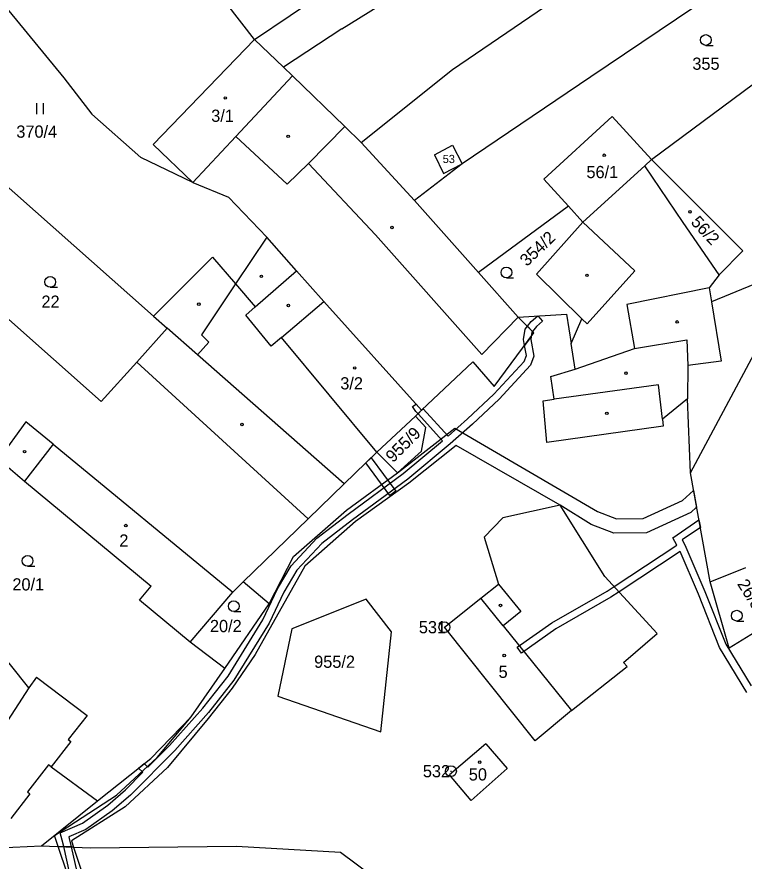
# Model space of a CAD drawing. Extents: x -749173 to -746119, y -1132678 to -1130338.
# Drawn here: x -747928.4 to -747827.1, y -1130958.5 to -1130840.9 of the extents above; entities that cross this region are included whole.
import ezdxf

# ---------------------------------------------------------------- set-up
doc = ezdxf.new("R2010")
doc.units = 0
for name, color, linetype in [('Vrstva 1', 7, 'Continuous'), ('Vrstva 17', 7, 'Continuous'), ('Vrstva 18', 7, 'Continuous'), ('Vrstva 19', 7, 'Continuous'), ('Vrstva 24', 7, 'Continuous'), ('Vrstva 25', 7, 'Continuous'), ('Vrstva 3', 7, 'Continuous'), ('Vrstva 30', 7, 'Continuous'), ('Vrstva 37', 7, 'Continuous'), ('Vrstva 4', 7, 'Continuous'), ('Vrstva 6', 7, 'Continuous'), ('Vrstva 62', 7, 'Continuous')]:
    doc.layers.add(name, color=color, linetype=linetype)

msp = doc.modelspace()

# ---------------------------------------------------------------- linework, layer by layer
at = {"layer": 'Vrstva 1'}
for p, q in [((-747831.83, -1130919.6), (-747826.88, -1130917.6)), ((-747829.18, -1130928.84), (-747831.83, -1130919.6)), ((-747822.73, -1130924.82), (-747829.18, -1130928.84))]:
    msp.add_line(p, q, dxfattribs=at)
for points in [[(-747867.74, -1130848.23), (-747820.55, -1130816.09)], [(-747812.81, -1130825.22), (-747848.46, -1130849.27)], [(-747937.23, -1130830.7), (-747921.89, -1130849.4)], [(-747840.03, -1130860.79), (-747804.38, -1130834.32)], [(-747895.31, -1130844.05), (-747899.19, -1130839.1)], [(-747895.31, -1130844.05), (-747909.44, -1130858.68)], [(-747891.29, -1130847.94), (-747895.31, -1130844.05)], [(-747890.05, -1130849.13), (-747891.29, -1130847.94)], [(-747880.46, -1130858.39), (-747867.74, -1130848.23)], [(-747921.89, -1130849.4), (-747917.99, -1130854.46)], [(-747890.05, -1130849.13), (-747882.73, -1130856.2)], [(-747848.46, -1130849.27), (-747866.39, -1130861.37)], [(-747917.99, -1130854.46), (-747911.17, -1130860.49)], [(-747845.48, -1130854.8), (-747855.03, -1130863.49)], [(-747845.48, -1130854.8), (-747840.03, -1130860.79)], [(-747880.46, -1130858.39), (-747882.73, -1130856.2)], [(-747909.44, -1130858.68), (-747903.93, -1130864)], [(-747880.46, -1130858.39), (-747873.03, -1130866.5)], [(-747870.26, -1130860.14), (-747867.74, -1130858.78)], [(-747867.74, -1130858.78), (-747866.39, -1130861.37)], [(-747870.26, -1130860.14), (-747868.98, -1130862.72)], [(-747903.93, -1130864), (-747911.17, -1130860.49)], [(-747840.03, -1130860.79), (-747840.96, -1130861.66)], [(-747840.03, -1130860.79), (-747827.3, -1130873.5)], [(-747866.39, -1130861.37), (-747873.03, -1130866.5)], [(-747868.98, -1130862.72), (-747866.39, -1130861.37)], [(-747835.61, -1130869.57), (-747840.96, -1130861.66)], [(-747931.2, -1130863.28), (-747912.7, -1130879.65)], [(-747851.6, -1130867.26), (-747855.03, -1130863.49)], [(-747903.93, -1130864), (-747898.96, -1130866.03)], [(-747893.59, -1130871.58), (-747898.96, -1130866.03)], [(-747864.12, -1130876.49), (-747873.03, -1130866.5)], [(-747851.6, -1130867.26), (-747864.12, -1130876.49)], [(-747849.58, -1130869.48), (-747851.6, -1130867.26)], [(-747849.58, -1130869.48), (-747856.02, -1130876.74)], [(-747830.59, -1130876.82), (-747835.61, -1130869.57)], [(-747893.59, -1130871.58), (-747897.97, -1130878.1)], [(-747889.47, -1130876.3), (-747893.59, -1130871.58)], [(-747827.3, -1130873.5), (-747830.59, -1130876.82)], [(-747909.4, -1130882.58), (-747901.18, -1130874.36)], [(-747901.18, -1130874.36), (-747897.97, -1130878.1)], [(-747889.47, -1130876.3), (-747885.64, -1130880.57)], [(-747858.58, -1130882.72), (-747864.12, -1130876.49)], [(-747916.7, -1130894.49), (-747936.25, -1130877.17)], [(-747856.02, -1130876.74), (-747849.73, -1130882.95)], [(-747830.59, -1130876.82), (-747832, -1130878.65)], [(-747832, -1130878.65), (-747831.64, -1130880.59)], [(-747825.65, -1130878.15), (-747831.64, -1130880.59)], [(-747912.7, -1130879.65), (-747909.4, -1130882.58)], [(-747885.64, -1130880.57), (-747872.04, -1130895.7)], [(-747831.64, -1130880.59), (-747830.29, -1130888.84)], [(-747858.58, -1130882.72), (-747851.86, -1130882.31)], [(-747851.86, -1130882.31), (-747851.22, -1130886.4)], [(-747909.4, -1130882.58), (-747907.48, -1130884.27)], [(-747856.4, -1130884.91), (-747858.58, -1130882.72)], [(-747851.22, -1130886.4), (-747849.73, -1130882.95)], [(-747907.48, -1130884.27), (-747911.73, -1130888.98)], [(-747903.24, -1130887.99), (-747907.48, -1130884.27)], [(-747861.93, -1130892.38), (-747856.4, -1130884.91)], [(-747850.63, -1130889.96), (-747851.22, -1130886.4)], [(-747882.81, -1130905.92), (-747903.24, -1130887.99)], [(-747834.6, -1130904.4), (-747825.73, -1130887.83)], [(-747911.73, -1130888.98), (-747916.7, -1130894.49)], [(-747872.04, -1130895.7), (-747864.89, -1130888.95)], [(-747864.89, -1130888.95), (-747861.93, -1130892.38)], [(-747834.94, -1130889.44), (-747834.99, -1130894.09)], [(-747830.29, -1130888.84), (-747834.94, -1130889.44)], [(-747854.03, -1130890.99), (-747850.63, -1130889.96)], [(-747853.59, -1130894.17), (-747854.03, -1130890.99)], [(-747855.12, -1130894.39), (-747853.59, -1130894.17)], [(-747834.99, -1130894.09), (-747838.48, -1130896.91)], [(-747834.6, -1130904.4), (-747834.99, -1130894.09)], [(-747854.58, -1130900.2), (-747855.12, -1130894.39)], [(-747872.89, -1130896.5), (-747878.28, -1130901.53)], [(-747872.89, -1130896.5), (-747872.04, -1130895.7)], [(-747871.47, -1130898.11), (-747872.89, -1130896.5)], [(-747838.48, -1130896.91), (-747838.4, -1130897.9)], [(-747872.07, -1130901.37), (-747871.47, -1130898.11)], [(-747838.4, -1130897.9), (-747854.58, -1130900.2)], [(-747882.81, -1130905.92), (-747878.28, -1130901.53)], [(-747878.28, -1130901.53), (-747875.4, -1130904.41)], [(-747875.4, -1130904.41), (-747872.07, -1130901.37)], [(-747930.99, -1130902.52), (-747927.35, -1130905.55)], [(-747831.83, -1130919.6), (-747834.6, -1130904.4)], [(-747927.35, -1130905.55), (-747909.73, -1130920.21)], [(-747887.85, -1130910.81), (-747882.81, -1130905.92)], [(-747852.72, -1130908.9), (-747860.71, -1130910.68)], [(-747846.52, -1130918.84), (-747852.72, -1130908.9)], [(-747860.71, -1130910.68), (-747863.35, -1130913.36)], [(-747896.9, -1130919.58), (-747887.85, -1130910.81)], [(-747863.35, -1130913.36), (-747861.32, -1130919.89)], [(-747926.76, -1130934.36), (-747939.55, -1130918.32)], [(-747839.22, -1130926.8), (-747846.52, -1130918.84)], [(-747896.9, -1130919.58), (-747898.32, -1130921.01)], [(-747893.27, -1130922.65), (-747896.9, -1130919.58)], [(-747863.78, -1130921.85), (-747861.32, -1130919.89)], [(-747911.33, -1130922.13), (-747909.73, -1130920.21)], [(-747904.3, -1130927.98), (-747898.32, -1130921.01)], [(-747904.3, -1130927.98), (-747911.33, -1130922.13)], [(-747879.78, -1130921.99), (-747890.11, -1130926.12)], [(-747876.24, -1130926.56), (-747879.78, -1130921.99)], [(-747868.87, -1130925.9), (-747863.78, -1130921.85)], [(-747899.44, -1130931.65), (-747893.27, -1130922.65)], [(-747856.24, -1130941.74), (-747868.87, -1130925.9)], [(-747890.11, -1130926.12), (-747892.05, -1130935.51)], [(-747877.73, -1130940.47), (-747876.24, -1130926.56)], [(-747843.9, -1130930.84), (-747839.22, -1130926.8)], [(-747899.44, -1130931.65), (-747904.3, -1130927.98)], [(-747904.14, -1130938.37), (-747899.44, -1130931.65)], [(-747851.16, -1130937.49), (-747843.41, -1130931.39)], [(-747843.41, -1130931.39), (-747843.9, -1130930.84)], [(-747925.67, -1130932.84), (-747926.76, -1130934.36)], [(-747925.67, -1130932.84), (-747918.64, -1130938.18)], [(-747892.05, -1130935.51), (-747877.73, -1130940.47)], [(-747851.16, -1130937.49), (-747856.24, -1130941.74)], [(-747918.64, -1130938.18), (-747921.26, -1130941.54)], [(-747909.76, -1130944.17), (-747904.14, -1130938.37)], [(-747920.91, -1130941.82), (-747923.65, -1130945.33)], [(-747921.26, -1130941.54), (-747920.91, -1130941.82)], [(-747863.09, -1130942.14), (-747868.17, -1130946.48)], [(-747863.09, -1130942.14), (-747860.11, -1130945.6)], [(-747917.18, -1130950.1), (-747909.76, -1130944.17)], [(-747923.65, -1130945.33), (-747917.18, -1130950.1)], [(-747860.11, -1130945.6), (-747865.14, -1130950.05)], [(-747865.14, -1130950.05), (-747868.17, -1130946.48)], [(-747924.97, -1130956.33), (-747917.18, -1130950.1)], [(-747935.01, -1130956.79), (-747924.97, -1130956.33)], [(-747924.97, -1130956.33), (-747918.19, -1130956.61)], [(-747918.19, -1130956.61), (-747897.81, -1130956.39)], [(-747897.81, -1130956.39), (-747883.35, -1130957.23)], [(-747883.35, -1130957.23), (-747867.68, -1130968.89)]]:
    msp.add_lwpolyline(points, dxfattribs=at)
at = {"layer": 'Vrstva 24'}
for p, q in [((-747868.92, -1130925.9), (-747868.82, -1130925.9)), ((-747868, -1130945.95), (-747867.9, -1130945.95))]:
    msp.add_line(p, q, dxfattribs=at)
for centre in [(-747868.87, -1130925.9), (-747867.95, -1130945.95)]:
    msp.add_circle(centre, 0.756, dxfattribs=at)
at = {"layer": 'Vrstva 25'}
for p, q in [((-747832.45, -1130844.88), (-747831.45, -1130844.88)), ((-747925.7, -1130852.94), (-747925.7, -1130854.44)), ((-747924.7, -1130854.44), (-747924.7, -1130852.94)), ((-747860.23, -1130877.25), (-747859.23, -1130877.25)), ((-747923.78, -1130878.57), (-747922.78, -1130878.57)), ((-747926.93, -1130917.42), (-747925.93, -1130917.42)), ((-747898.21, -1130923.72), (-747897.21, -1130923.72)), ((-747828.14, -1130925.05), (-747827.14, -1130925.05))]:
    msp.add_line(p, q, dxfattribs=at)
for centre, radius in [((-747832.45, -1130844.13), 0.75), ((-747899.39, -1130852.2), 0.175), ((-747890.63, -1130857.54), 0.175), ((-747846.6, -1130860.18), 0.175), ((-747876.17, -1130870.25), 0.175), ((-747860.23, -1130876.5), 0.75), ((-747923.78, -1130877.82), 0.75), ((-747894.36, -1130877.04), 0.175), ((-747849.01, -1130876.91), 0.175), ((-747903.07, -1130880.92), 0.175), ((-747890.6, -1130881.1), 0.175), ((-747836.45, -1130883.39), 0.175), ((-747881.36, -1130889.8), 0.175), ((-747843.58, -1130890.52), 0.175), ((-747846.24, -1130896.13), 0.175), ((-747897.07, -1130897.68), 0.175), ((-747927.35, -1130901.46), 0.175), ((-747913.24, -1130911.75), 0.175), ((-747926.93, -1130916.67), 0.75), ((-747898.21, -1130922.97), 0.75), ((-747861.06, -1130922.87), 0.175), ((-747828.14, -1130924.3), 0.75), ((-747860.53, -1130929.85), 0.175), ((-747863.95, -1130944.69), 0.175)]:
    msp.add_circle(centre, radius, dxfattribs=at)
at = {"layer": 'Vrstva 3'}
for points in [[(-747895.31, -1130844.05), (-747909.44, -1130858.68)], [(-747891.29, -1130847.94), (-747895.31, -1130844.05)], [(-747890.05, -1130849.13), (-747891.29, -1130847.94)], [(-747890.05, -1130849.13), (-747897.92, -1130857.56)], [(-747845.48, -1130854.8), (-747855.03, -1130863.49)], [(-747845.48, -1130854.8), (-747840.03, -1130860.79)], [(-747897.92, -1130857.56), (-747903.93, -1130864)], [(-747909.44, -1130858.68), (-747903.93, -1130864)], [(-747840.03, -1130860.79), (-747840.96, -1130861.66)], [(-747840.96, -1130861.66), (-747849.58, -1130869.48)], [(-747851.6, -1130867.26), (-747855.03, -1130863.49)], [(-747849.58, -1130869.48), (-747851.6, -1130867.26)], [(-747891.57, -1130885.56), (-747885.64, -1130880.57)], [(-747885.64, -1130880.57), (-747872.04, -1130895.7)], [(-747878.28, -1130901.53), (-747891.57, -1130885.56)], [(-747872.89, -1130896.5), (-747878.28, -1130901.53)], [(-747872.89, -1130896.5), (-747872.04, -1130895.7)], [(-747923.37, -1130900.43), (-747927.35, -1130905.55)], [(-747923.37, -1130900.43), (-747898.32, -1130921.01)], [(-747927.35, -1130905.55), (-747909.73, -1130920.21)], [(-747911.33, -1130922.13), (-747909.73, -1130920.21)], [(-747904.3, -1130927.98), (-747898.32, -1130921.01)], [(-747904.3, -1130927.98), (-747911.33, -1130922.13)], [(-747868.87, -1130925.9), (-747863.78, -1130921.85)], [(-747860.68, -1130925.7), (-747863.78, -1130921.85)], [(-747856.24, -1130941.74), (-747868.87, -1130925.9)], [(-747860.68, -1130925.7), (-747851.16, -1130937.49)], [(-747851.16, -1130937.49), (-747856.24, -1130941.74)], [(-747863.09, -1130942.14), (-747868.17, -1130946.48)], [(-747863.09, -1130942.14), (-747860.11, -1130945.6)], [(-747860.11, -1130945.6), (-747865.14, -1130950.05)], [(-747865.14, -1130950.05), (-747868.17, -1130946.48)]]:
    msp.add_lwpolyline(points, dxfattribs=at)
at = {"layer": 'Vrstva 30'}
for p, q in [((-747875.4, -1130904.41), (-747867.4, -1130898.17)), ((-747867.4, -1130898.17), (-747847.54, -1130909.78)), ((-747867.22, -1130900.59), (-747873.81, -1130905.83)), ((-747852.72, -1130908.9), (-747867.22, -1130900.59)), ((-747879.83, -1130903.03), (-747879.08, -1130902.3)), ((-747879.08, -1130902.3), (-747875.62, -1130906.96)), ((-747876.46, -1130907.58), (-747879.83, -1130903.03)), ((-747882.51, -1130909.62), (-747875.4, -1130904.41)), ((-747873.81, -1130905.83), (-747881.27, -1130911.18)), ((-747875.62, -1130906.96), (-747876.46, -1130907.58)), ((-747841.17, -1130910.78), (-747835.68, -1130908.26)), ((-747848.4, -1130911.58), (-747852.72, -1130908.9)), ((-747889.87, -1130916.08), (-747882.51, -1130909.62)), ((-747847.54, -1130909.78), (-747844.9, -1130910.79)), ((-747834.56, -1130909.94), (-747840.73, -1130912.78)), ((-747881.27, -1130911.18), (-747888.33, -1130917.38)), ((-747845.26, -1130912.79), (-747848.4, -1130911.58)), ((-747844.9, -1130910.79), (-747841.17, -1130910.78)), ((-747840.73, -1130912.78), (-747845.26, -1130912.79)), ((-747893.27, -1130922.65), (-747889.87, -1130916.08)), ((-747888.33, -1130917.38), (-747895.25, -1130929.7)), ((-747899.44, -1130931.65), (-747893.27, -1130922.65)), ((-747895.25, -1130929.7), (-747898.41, -1130934.37)), ((-747904.14, -1130938.37), (-747899.44, -1130931.65)), ((-747898.41, -1130934.37), (-747901.78, -1130938.63)), ((-747908.89, -1130944.06), (-747904.14, -1130938.37)), ((-747901.78, -1130938.63), (-747907.43, -1130945.44)), ((-747914.54, -1130949.31), (-747908.89, -1130944.06)), ((-747907.43, -1130945.44), (-747913.32, -1130950.91)), ((-747923.2, -1130954.91), (-747914.54, -1130949.31)), ((-747913.32, -1130950.91), (-747920.83, -1130955.66)), ((-747922.69, -1130956.42), (-747923.2, -1130954.91)), ((-747920.83, -1130955.66), (-747920.54, -1130956.51))]:
    msp.add_line(p, q, dxfattribs=at)
for points in [[(-747857.31, -1130883.99), (-747856.77, -1130883.32)], [(-747856.77, -1130883.32), (-747855.86, -1130882.55)], [(-747855.2, -1130883.29), (-747856.05, -1130884.02)], [(-747855.86, -1130882.55), (-747855.2, -1130883.29)], [(-747857.86, -1130885.86), (-747857.63, -1130884.39)], [(-747857.63, -1130884.39), (-747857.31, -1130883.99)], [(-747857.31, -1130883.99), (-747856.6, -1130884.71)], [(-747856.6, -1130884.71), (-747857.31, -1130883.99)], [(-747856.69, -1130884.81), (-747856.78, -1130885.42)], [(-747856.6, -1130884.71), (-747856.69, -1130884.81)], [(-747856.05, -1130884.02), (-747856.6, -1130884.71)], [(-747857.71, -1130886.67), (-747857.86, -1130885.86)], [(-747856.78, -1130885.42), (-747857.71, -1130886.67)], [(-747857.71, -1130886.67), (-747856.78, -1130885.42)], [(-747856.78, -1130885.42), (-747856.84, -1130885.86)], [(-747856.84, -1130885.86), (-747856.41, -1130888.14)], [(-747857.45, -1130888.06), (-747857.71, -1130886.67)], [(-747857.74, -1130888.89), (-747857.45, -1130888.06)], [(-747856.41, -1130888.14), (-747856.86, -1130889.41)], [(-747861.97, -1130893.47), (-747857.74, -1130888.89)], [(-747856.86, -1130889.41), (-747861.26, -1130894.17)], [(-747865.63, -1130896.89), (-747861.97, -1130893.47)], [(-747861.26, -1130894.17), (-747864.97, -1130897.63)], [(-747873.3, -1130895.19), (-747872.81, -1130894.85)], [(-747872.83, -1130895.85), (-747873.3, -1130895.19)], [(-747872.81, -1130894.85), (-747872.04, -1130895.7)], [(-747872.54, -1130896.17), (-747872.83, -1130895.85)], [(-747872.04, -1130895.7), (-747872.54, -1130896.17)], [(-747872.54, -1130896.17), (-747872.04, -1130895.7)], [(-747869.12, -1130899.93), (-747872.54, -1130896.17)], [(-747872.04, -1130895.7), (-747871.81, -1130895.49)], [(-747871.81, -1130895.49), (-747868.36, -1130899.28)], [(-747868.36, -1130899.28), (-747865.63, -1130896.89)], [(-747864.97, -1130897.63), (-747868.07, -1130900.36)], [(-747874.59, -1130904.51), (-747869.12, -1130899.93)], [(-747868.07, -1130900.36), (-747873.97, -1130905.31)], [(-747882.26, -1130910.17), (-747874.59, -1130904.51)], [(-747873.97, -1130905.31), (-747881.66, -1130910.97)], [(-747835.68, -1130908.26), (-747834.15, -1130906.85), (-747833.73, -1130909.18), (-747834.56, -1130909.94)], [(-747886.63, -1130913.52), (-747882.26, -1130910.17)], [(-747881.66, -1130910.97), (-747885.95, -1130914.26)], [(-747837.05, -1130913.45), (-747833.41, -1130910.94)], [(-747833.41, -1130910.94), (-747833.21, -1130912.02)], [(-747833.21, -1130912.02), (-747835.73, -1130913.75)], [(-747890.21, -1130917.35), (-747886.63, -1130913.52)], [(-747885.95, -1130914.26), (-747889.41, -1130917.95)], [(-747836.47, -1130914.48), (-747837.05, -1130913.45)], [(-747835.73, -1130913.75), (-747835.36, -1130914.42)], [(-747845.23, -1130920.25), (-747836.47, -1130914.48)], [(-747836.04, -1130915.38), (-747844.54, -1130921)], [(-747833.49, -1130921.3), (-747836.04, -1130915.38)], [(-747835.36, -1130914.42), (-747832.57, -1130920.92)], [(-747892.1, -1130920.55), (-747890.21, -1130917.35)], [(-747889.41, -1130917.95), (-747891.22, -1130921.03)], [(-747894.18, -1130924.87), (-747892.1, -1130920.55)], [(-747891.22, -1130921.03), (-747893.3, -1130925.35)], [(-747853.88, -1130925.3), (-747846.21, -1130920.9)], [(-747846.21, -1130920.9), (-747845.23, -1130920.25)], [(-747844.54, -1130921), (-747845.67, -1130921.74)], [(-747830.55, -1130928.71), (-747833.49, -1130921.3)], [(-747832.57, -1130920.92), (-747829.65, -1130928.27)], [(-747845.67, -1130921.74), (-747853.35, -1130926.14)], [(-747899, -1130932.71), (-747894.18, -1130924.87)], [(-747893.3, -1130925.35), (-747898.18, -1130933.29)], [(-747858.73, -1130928.68), (-747853.88, -1130925.3)], [(-747853.35, -1130926.14), (-747858.15, -1130929.5)], [(-747829.65, -1130928.27), (-747826.14, -1130934.07)], [(-747858.15, -1130929.5), (-747858.73, -1130928.68)], [(-747826.76, -1130934.98), (-747830.55, -1130928.71)], [(-747902.51, -1130937.16), (-747899, -1130932.71)], [(-747898.18, -1130933.29), (-747901.75, -1130937.8)], [(-747907.18, -1130942.37), (-747902.51, -1130937.16)], [(-747901.75, -1130937.8), (-747906.44, -1130943.05)], [(-747910.17, -1130945.39), (-747907.18, -1130942.37)], [(-747906.44, -1130943.05), (-747912.59, -1130949.3)], [(-747911.46, -1130945.53), (-747910.67, -1130944.9)], [(-747910.87, -1130946.11), (-747911.46, -1130945.53)], [(-747910.67, -1130944.9), (-747910.17, -1130945.39)], [(-747913.27, -1130948.56), (-747910.87, -1130946.11)], [(-747915.76, -1130950.7), (-747913.27, -1130948.56)], [(-747912.59, -1130949.3), (-747915.14, -1130951.48)], [(-747919.29, -1130953.17), (-747915.76, -1130950.7)], [(-747915.14, -1130951.48), (-747918.81, -1130954.05)], [(-747922.38, -1130954.54), (-747919.29, -1130953.17)], [(-747918.81, -1130954.05), (-747921.18, -1130955.1)], [(-747922.1, -1130955.58), (-747922.38, -1130954.54)], [(-747921.18, -1130955.1), (-747921.13, -1130955.34)], [(-747921.13, -1130955.34), (-747920.87, -1130956.5)], [(-747922.69, -1130956.42), (-747920.54, -1130956.51), (-747918.16, -1130963.58), (-747913.86, -1130962.14), (-747913.23, -1130964.04), (-747917.23, -1130965.37), (-747920.72, -1130964.55), (-747920.04, -1130964.27), (-747922.69, -1130956.42)], [(-747920.54, -1130956.51), (-747922.69, -1130956.42)], [(-747921.9, -1130956.46), (-747922.1, -1130955.58)], [(-747921.9, -1130956.46), (-747920.87, -1130956.5), (-747919.06, -1130964.49)], [(-747920.23, -1130964.04), (-747921.9, -1130956.46)], [(-747920.87, -1130956.5), (-747921.9, -1130956.46)]]:
    msp.add_lwpolyline(points, dxfattribs=at)
at = {"layer": 'Vrstva 37'}
for centre in [(-747899.39, -1130852.2), (-747846.6, -1130860.18), (-747881.36, -1130889.8), (-747913.24, -1130911.75), (-747860.53, -1130929.85), (-747863.95, -1130944.69)]:
    msp.add_circle(centre, 0.175, dxfattribs=at)
at = {"layer": 'Vrstva 4'}
for points in [[(-747890.05, -1130849.13), (-747897.92, -1130857.56)], [(-747887.82, -1130861.32), (-747882.73, -1130856.2)], [(-747897.92, -1130857.56), (-747903.93, -1130864)], [(-747897.92, -1130857.56), (-747890.77, -1130864.23)], [(-747887.82, -1130861.32), (-747890.77, -1130864.23)], [(-747878.46, -1130871.28), (-747887.82, -1130861.32)], [(-747840.96, -1130861.66), (-747849.58, -1130869.48)], [(-747842.34, -1130876.27), (-747849.58, -1130869.48)], [(-747863.67, -1130887.95), (-747878.46, -1130871.28)], [(-747895.21, -1130881.31), (-747889.47, -1130876.3)], [(-747848.96, -1130883.68), (-747842.34, -1130876.27)], [(-747897.97, -1130878.1), (-747902.71, -1130885.17)], [(-747897.97, -1130878.1), (-747895.21, -1130881.31)], [(-747832, -1130878.65), (-747843.45, -1130880.95)], [(-747896.52, -1130882.45), (-747895.21, -1130881.31)], [(-747891.57, -1130885.56), (-747885.64, -1130880.57)], [(-747843.45, -1130880.95), (-747842.38, -1130887.09)], [(-747892.98, -1130886.77), (-747896.52, -1130882.45)], [(-747858.58, -1130882.72), (-747863.67, -1130887.95)], [(-747849.73, -1130882.95), (-747848.96, -1130883.68)], [(-747902.71, -1130885.17), (-747901.69, -1130886.19)], [(-747891.57, -1130885.56), (-747892.98, -1130886.77)], [(-747878.28, -1130901.53), (-747891.57, -1130885.56)], [(-747842.38, -1130887.09), (-747835.08, -1130885.88)], [(-747835.08, -1130885.88), (-747834.94, -1130889.44)], [(-747901.69, -1130886.19), (-747903.24, -1130887.99)], [(-747850.63, -1130889.96), (-747842.38, -1130887.09)], [(-747887.85, -1130910.81), (-747911.73, -1130888.98)], [(-747839.02, -1130892.13), (-747853.59, -1130894.17)], [(-747838.48, -1130896.91), (-747839.02, -1130892.13)], [(-747927.18, -1130897.3), (-747930.99, -1130902.52)], [(-747923.37, -1130900.43), (-747927.18, -1130897.3)], [(-747923.37, -1130900.43), (-747927.35, -1130905.55)], [(-747923.37, -1130900.43), (-747898.32, -1130921.01)], [(-747861.32, -1130919.89), (-747858.22, -1130923.72)], [(-747860.68, -1130925.7), (-747863.78, -1130921.85)], [(-747858.22, -1130923.72), (-747860.68, -1130925.7)], [(-747860.68, -1130925.7), (-747851.16, -1130937.49)], [(-747926.76, -1130934.36), (-747931.2, -1130941.16)], [(-747924, -1130945.06), (-747926.95, -1130948.85)], [(-747923.65, -1130945.33), (-747924, -1130945.06)], [(-747926.6, -1130949.12), (-747929.28, -1130952.56)], [(-747926.95, -1130948.85), (-747926.6, -1130949.12)]]:
    msp.add_lwpolyline(points, dxfattribs=at)
at = {"layer": 'Vrstva 6'}
for points in [[(-747883.17, -1130842.59), (-747829.36, -1130809.14)], [(-747895.31, -1130844.05), (-747885.37, -1130837.32)], [(-747883.17, -1130842.59), (-747891.29, -1130847.94)]]:
    msp.add_lwpolyline(points, dxfattribs=at)
at = {"layer": 'Vrstva 62'}
msp.add_circle((-747834.66, -1130868.06), 0.175, dxfattribs=at)

# ---------------------------------------------------------------- texts
at = {"layer": 'Vrstva 17'}
for s, p in [('531', (-747872.43, -1130926.75)), ('532', (-747871.87, -1130946.8))]:
    msp.add_text(s, height=1.7, dxfattribs=at).set_placement(p)
at = {"layer": 'Vrstva 18'}
for s, p in [('355', (-747834.33, -1130848.28)), ('370/4', (-747928.5, -1130857.74)), ('22', (-747925, -1130881.42)), ('20/1', (-747929.05, -1130920.79)), ('20/2', (-747901.53, -1130926.59)), ('955/2', (-747887.01, -1130931.56))]:
    msp.add_text(s, height=1.7, dxfattribs=at).set_placement(p)
for s, rotation, p in [('354/2', 43.673, (-747857.37, -1130875.75)), ('955/9', 45, (-747876.04, -1130903.08)), ('26/3', 302.0911, (-747828.14, -1130919.87))]:
    msp.add_text(s, height=1.7, rotation=rotation, dxfattribs=at).set_placement(p)
at = {"layer": 'Vrstva 19'}
for s, height, p in [('3/1', 1.7, (-747901.35, -1130855.53)), ('53', 1.14, (-747869.1, -1130861.27)), ('56/1', 1.7, (-747849.08, -1130863.37)), ('3/2', 1.7, (-747883.37, -1130892.79)), ('2', 1.7, (-747914.15, -1130914.68)), ('5', 1.7, (-747861.32, -1130932.96)), ('50', 1.7, (-747865.47, -1130947.25))]:
    msp.add_text(s, height=height, dxfattribs=at).set_placement(p)
msp.add_text('56/2', height=1.7, rotation=312.8317, dxfattribs=at).set_placement((-747834.64, -1130869.59))

doc.saveas('drawing.dxf')
